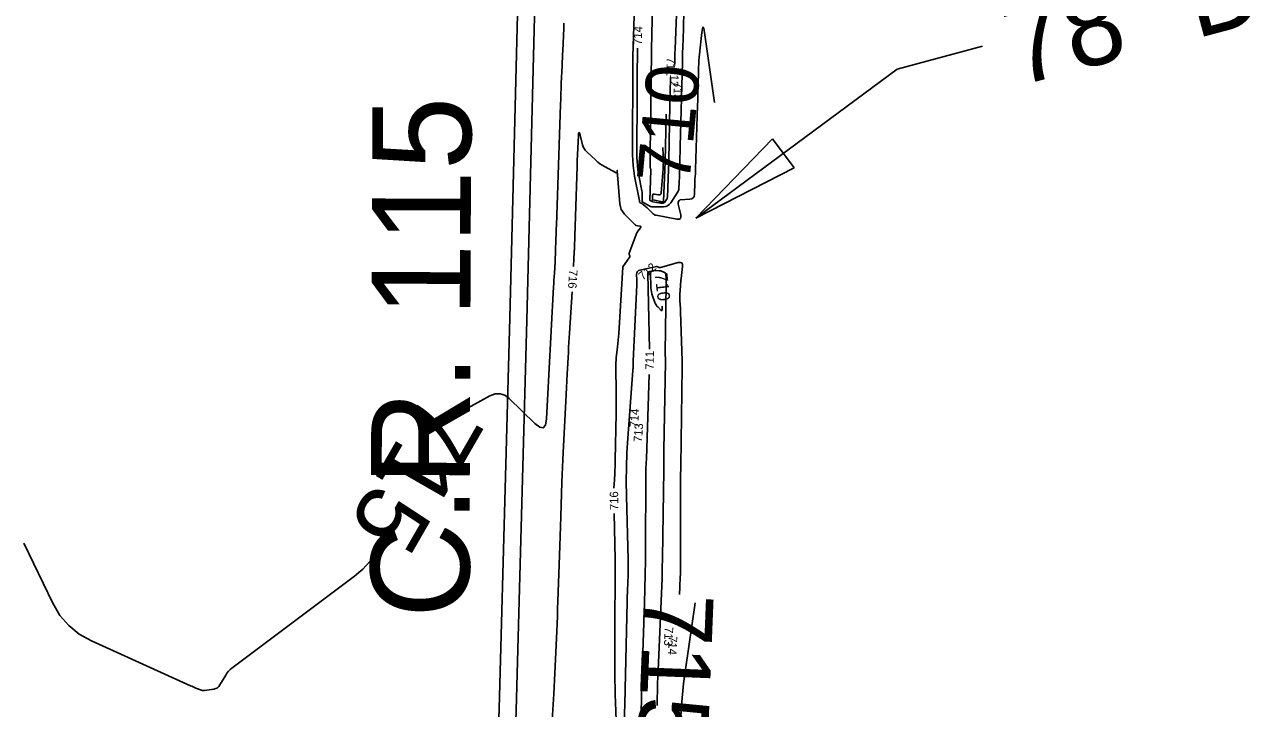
# Model space of a CAD drawing. Extents: x -361782338 to 28259792, y -263199453 to 8342113.
# Drawn here: x 1403593 to 1404176, y 577718 to 578042 of the extents above; entities that cross this region are included whole.
import ezdxf

# ---------------------------------------------------------------- set-up
doc = ezdxf.new("R2010")
doc.units = 0
for name, color, linetype in [('DT_X_Contour_Minor', 7, 'Continuous'), ('Level 19', 7, 'Continuous'), ('Level 40', 7, 'Continuous'), ('Level 56', 7, 'Continuous')]:
    doc.layers.add(name, color=color, linetype=linetype)

msp = doc.modelspace()

# ---------------------------------------------------------------- linework, layer by layer
at = {"layer": 'DT_X_Contour_Minor'}
for points in [[(1403882.24, 578075.26), (1403880.6, 578027.15), (1403880.59, 578027), (1403880.59, 578026.85), (1403880.58, 578026.7), (1403880.58, 578026.55), (1403880.57, 578026.07), (1403880.57, 578025.96), (1403880.57, 578025.86), (1403880.57, 578025.75), (1403880.57, 578025.65), (1403880.56, 578024.98), (1403880.55, 578024.84), (1403880.55, 578024.7), (1403880.55, 578024.56), (1403880.55, 578024.42), (1403880.5, 577980.69), (1403880.55, 577978.11), (1403880.74, 577975.55), (1403881.04, 577973), (1403881.47, 577970.46), (1403883.75, 577958.75), (1403883.76, 577958.69), (1403883.76, 577958.63), (1403883.77, 577958.57), (1403883.77, 577958.51), (1403883.76, 577958.31), (1403883.76, 577958.27), (1403883.77, 577958.24), (1403883.79, 577958.21), (1403883.82, 577958.18), (1403883.99, 577958.04), (1403884.03, 577958.01), (1403884.07, 577957.99), (1403884.11, 577957.96), (1403884.15, 577957.94), (1403884.93, 577957.49), (1403885.09, 577957.39), (1403885.25, 577957.29), (1403885.41, 577957.17), (1403885.56, 577957.05), (1403887.36, 577955.49), (1403887.74, 577955.15), (1403888.12, 577954.81), (1403888.49, 577954.46), (1403888.86, 577954.11), (1403890.25, 577952.74), (1403890.56, 577952.47), (1403890.9, 577952.26), (1403891.27, 577952.1), (1403891.67, 577952), (1403901.48, 577950.2), (1403902.51, 577950.15), (1403903.16, 577950.46), (1403903.43, 577951.13), (1403903.33, 577952.16)], [(1403882.87, 578031.13), (1403882.82, 578028.02), (1403882.8, 578026.91), (1403882.78, 578025.81), (1403882.77, 578024.7), (1403882.75, 578023.6), (1403882.65, 578016.61), (1403882.64, 578015.11), (1403882.62, 578013.61), (1403882.61, 578012.11), (1403882.61, 578010.61), (1403882.57, 577979.48), (1403882.61, 577977.48), (1403882.76, 577975.5), (1403882.99, 577973.52), (1403883.33, 577971.55), (1403884.88, 577963.54), (1403884.98, 577962.96), (1403885.04, 577962.38), (1403885.07, 577961.79), (1403885.07, 577961.2), (1403884.99, 577958.54), (1403884.99, 577958.5), (1403885, 577958.45), (1403885.03, 577958.42), (1403885.06, 577958.39), (1403885.18, 577958.29), (1403885.21, 577958.27), (1403885.24, 577958.25), (1403885.26, 577958.23), (1403885.29, 577958.22), (1403888.68, 577956.28), (1403888.8, 577956.22), (1403888.92, 577956.17), (1403889.05, 577956.13), (1403889.18, 577956.1), (1403889.61, 577956.02), (1403889.7, 577956.01), (1403889.8, 577956), (1403889.89, 577955.99), (1403889.99, 577955.99), (1403895.15, 577956), (1403896.2, 577956.12), (1403897.12, 577956.47), (1403897.91, 577957.05), (1403898.57, 577957.87), (1403901.99, 577963.14), (1403902.16, 577963.46), (1403902.29, 577963.79), (1403902.38, 577964.13), (1403902.42, 577964.49), (1403902.47, 577965.68), (1403902.48, 577965.94), (1403902.49, 577966.2), (1403902.5, 577966.45), (1403902.51, 577966.71), (1403902.86, 577975.56), (1403902.89, 577976.45), (1403902.92, 577977.35), (1403902.94, 577978.25), (1403902.96, 577979.14), (1403903.01, 577982.07), (1403903.03, 577982.7), (1403903.04, 577983.32), (1403903.05, 577983.95), (1403903.07, 577984.58), (1403904.09, 578024.68), (1403904.11, 578025.68), (1403904.14, 578026.68), (1403904.18, 578027.67), (1403904.21, 578028.67), (1403904.34, 578031.94), (1403904.36, 578032.63), (1403904.38, 578033.33), (1403904.4, 578034.03), (1403904.42, 578034.73), (1403905.37, 578074.7)], [(1403890.04, 578062.7), (1403889.61, 578036.78), (1403889.52, 578031.22), (1403889.43, 578025.67), (1403889.35, 578020.11), (1403889.27, 578014.56), (1403888.81, 577981.82), (1403888.8, 577981.08), (1403888.8, 577980.33), (1403888.79, 577979.58), (1403888.79, 577978.83), (1403888.79, 577975.86), (1403888.79, 577975.6), (1403888.81, 577975.34), (1403888.84, 577975.08), (1403888.89, 577974.83), (1403889.05, 577973.99), (1403889.08, 577973.81), (1403889.1, 577973.62), (1403889.11, 577973.44), (1403889.11, 577973.26), (1403888.67, 577959.12), (1403888.67, 577959.11), (1403888.68, 577959.1), (1403888.68, 577959.09), (1403888.69, 577959.08), (1403888.73, 577959.05), (1403888.73, 577959.05), (1403888.74, 577959.04), (1403888.75, 577959.04), (1403888.76, 577959.03), (1403889.44, 577958.64), (1403889.59, 577958.56), (1403889.75, 577958.5), (1403889.91, 577958.45), (1403890.07, 577958.41), (1403892.92, 577957.9), (1403893.22, 577957.85), (1403893.53, 577957.82), (1403893.84, 577957.8), (1403894.14, 577957.8), (1403895.15, 577957.8), (1403895.35, 577957.82), (1403895.53, 577957.89), (1403895.69, 577958), (1403895.82, 577958.16), (1403896.6, 577959.38), (1403896.75, 577959.65), (1403896.87, 577959.93), (1403896.94, 577960.22), (1403896.97, 577960.52), (1403897.54, 577973.69), (1403897.56, 577974.13), (1403897.58, 577974.57), (1403897.59, 577975.01), (1403897.61, 577975.44), (1403897.67, 577976.88), (1403897.68, 577977.19), (1403897.69, 577977.49), (1403897.7, 577977.8), (1403897.7, 577978.11), (1403898.36, 578012.79), (1403898.39, 578014.34), (1403898.42, 578015.89), (1403898.45, 578017.16)], [(1403900.41, 578022.93), (1403900.45, 578024.13), (1403900.51, 578026.37), (1403900.59, 578028.6), (1403900.67, 578030.84), (1403901.43, 578051.04)], [(1403797.76, 577857.75), (1403801.18, 577859.93), (1403812.96, 577866.41), (1403815.43, 577867.37), (1403817.78, 577867.48), (1403820.02, 577866.74), (1403822.14, 577865.15), (1403834.23, 577853.34), (1403836.52, 577851.57), (1403838.21, 577851.35), (1403839.3, 577852.66), (1403839.79, 577855.51), (1403843.1, 577918.08), (1403843.19, 577919.7), (1403843.28, 577921.33), (1403843.38, 577922.95), (1403843.48, 577924.57), (1403843.81, 577929.87), (1403843.87, 577931.01), (1403843.93, 577932.14), (1403843.98, 577933.28), (1403844.02, 577934.42), (1403844.24, 577941.24), (1403844.29, 577942.7), (1403844.34, 577944.16), (1403844.39, 577945.62), (1403844.44, 577947.09), (1403846.37, 578004.51), (1403846.46, 578007.03), (1403846.55, 578009.55), (1403846.65, 578012.07), (1403846.76, 578014.59), (1403847.12, 578022.82), (1403847.2, 578024.59), (1403847.28, 578026.35), (1403847.35, 578028.11), (1403847.43, 578029.88), (1403847.89, 578040.65), (1403848, 578042.96)], [(1403903.33, 577952.16), (1403902.06, 577957.31), (1403902.02, 577957.54), (1403902.03, 577957.77), (1403902.07, 577957.99), (1403902.16, 577958.21), (1403902.51, 577958.91), (1403902.59, 577959.04), (1403902.7, 577959.14), (1403902.84, 577959.2), (1403902.99, 577959.23), (1403907.69, 577959.64), (1403908.58, 577959.84), (1403909.22, 577960.27), (1403909.62, 577960.93), (1403909.77, 577961.83), (1403909.96, 577967.6), (1403909.98, 577968.21), (1403910.01, 577968.82), (1403910.05, 577969.42), (1403910.1, 577970.03), (1403910.28, 577972), (1403910.31, 577972.43), (1403910.34, 577972.85), (1403910.36, 577973.28), (1403910.37, 577973.7), (1403911.29, 578004), (1403911.36, 578006.27), (1403911.42, 578008.55), (1403911.47, 578010.83), (1403911.52, 578013.1), (1403911.68, 578020.54), (1403911.73, 578022.14), (1403911.82, 578023.73), (1403911.94, 578025.32), (1403912.09, 578026.9), (1403913.33, 578038.59), (1403913.61, 578040.47), (1403913.91, 578041.1), (1403914.24, 578040.48), (1403914.58, 578038.61), (1403919.34, 578005.4)], [(1403889.9, 577959.31), (1403889.91, 577959.31), (1403889.91, 577959.31), (1403889.91, 577959.31), (1403889.91, 577959.3), (1403889.91, 577959.3), (1403889.98, 577959.26), (1403890, 577959.25), (1403890.02, 577959.25), (1403890.03, 577959.24), (1403890.05, 577959.24), (1403894.71, 577958.41), (1403894.74, 577958.4), (1403894.77, 577958.4), (1403894.8, 577958.4), (1403894.84, 577958.4), (1403894.94, 577958.4), (1403894.96, 577958.4), (1403894.98, 577958.41), (1403895, 577958.42), (1403895.01, 577958.43), (1403895.09, 577958.56), (1403895.11, 577958.59), (1403895.12, 577958.62), (1403895.13, 577958.65), (1403895.13, 577958.68), (1403895.94, 577977.3), (1403895.94, 577977.33), (1403895.94, 577977.36), (1403895.94, 577977.38), (1403895.94, 577977.41), (1403895.95, 577977.5), (1403895.95, 577977.52), (1403895.95, 577977.54), (1403895.95, 577977.56), (1403895.95, 577977.58), (1403896.35, 577999.06), (1403896.35, 577999.86)], [(1403852.55, 577927.74), (1403852.75, 577931.49), (1403852.98, 577936.78), (1403853.17, 577942.08), (1403854.25, 577975.13), (1403854.25, 577975.39), (1403854.26, 577975.66), (1403854.27, 577975.93), (1403854.28, 577976.2), (1403854.31, 577977.07), (1403854.32, 577977.26), (1403854.32, 577977.45), (1403854.33, 577977.64), (1403854.34, 577977.83), (1403854.87, 577989.78), (1403854.96, 577990.85), (1403855.14, 577991.22), (1403855.38, 577990.89), (1403855.7, 577989.87), (1403856.86, 577985.39), (1403857.17, 577984.47), (1403857.59, 577983.61), (1403858.13, 577982.83), (1403858.79, 577982.11), (1403863.08, 577978.03), (1403864.02, 577977.19), (1403865.02, 577976.42), (1403866.06, 577975.73), (1403867.15, 577975.1), (1403872.73, 577972.13), (1403872.91, 577972.06), (1403873.03, 577972.08), (1403873.12, 577972.18), (1403873.16, 577972.36), (1403873.21, 577973.08), (1403873.22, 577973.2), (1403873.24, 577973.24), (1403873.25, 577973.2), (1403873.26, 577973.08), (1403874.49, 577957.43), (1403874.72, 577956.06), (1403875.17, 577954.79), (1403875.84, 577953.62), (1403876.74, 577952.55), (1403881.43, 577947.85), (1403881.44, 577947.84), (1403881.44, 577947.83), (1403881.45, 577947.81), (1403881.45, 577947.8), (1403881.46, 577947.75), (1403881.46, 577947.74), (1403881.47, 577947.73), (1403881.47, 577947.72), (1403881.48, 577947.71), (1403881.72, 577947.51), (1403881.75, 577947.48), (1403881.79, 577947.45), (1403881.82, 577947.42), (1403881.85, 577947.38), (1403881.96, 577947.28), (1403881.99, 577947.26), (1403882.01, 577947.24), (1403882.04, 577947.23), (1403882.07, 577947.22), (1403883.87, 577946.89), (1403884.18, 577946.79), (1403884.34, 577946.62), (1403884.34, 577946.4), (1403884.19, 577946.11), (1403883.02, 577944.45), (1403882.79, 577944.09), (1403882.57, 577943.72), (1403882.38, 577943.33), (1403882.22, 577942.93), (1403878.91, 577934.12), (1403878.86, 577933.93), (1403878.85, 577933.74), (1403878.88, 577933.55), (1403878.94, 577933.37), (1403879.23, 577932.77), (1403879.27, 577932.64), (1403879.28, 577932.52), (1403879.25, 577932.4), (1403879.18, 577932.28), (1403875.82, 577927.54), (1403875.81, 577927.52), (1403875.81, 577927.51), (1403875.82, 577927.5), (1403875.83, 577927.49), (1403875.88, 577927.46), (1403875.89, 577927.45), (1403875.89, 577927.45), (1403875.9, 577927.44), (1403875.9, 577927.42), (1403873.92, 577896.05), (1403873.81, 577894.45), (1403873.68, 577892.85), (1403873.53, 577891.26), (1403873.36, 577889.67), (1403872.77, 577884.48), (1403872.66, 577883.36)], [(1403894.87, 577984.05), (1403895.02, 577980.57), (1403895.07, 577978.94), (1403895.07, 577977.3), (1403895.02, 577975.67), (1403894.92, 577974.03), (1403894.09, 577962.65), (1403893.98, 577962.13), (1403893.72, 577961.79), (1403893.33, 577961.64), (1403892.8, 577961.66), (1403890.83, 577962.03), (1403890.46, 577962.05), (1403890.19, 577961.94), (1403890.03, 577961.7), (1403889.96, 577961.34), (1403889.9, 577959.31), (1403889.9, 577959.31), (1403889.9, 577959.31), (1403889.9, 577959.31), (1403889.9, 577959.31)], [(1403902.73, 577772.46), (1403902.78, 577773.52), (1403902.83, 577774.58), (1403902.87, 577775.64), (1403902.92, 577776.7), (1403903.07, 577780.17), (1403903.1, 577780.91), (1403903.12, 577781.65), (1403903.13, 577782.4), (1403903.14, 577783.14), (1403903.25, 577827.06), (1403903.25, 577827.67), (1403903.26, 577828.29), (1403903.26, 577828.91), (1403903.27, 577829.53), (1403903.3, 577831.55), (1403903.31, 577831.98), (1403903.32, 577832.41), (1403903.32, 577832.85), (1403903.33, 577833.28), (1403903.94, 577879.99), (1403903.94, 577880.28), (1403903.95, 577880.58), (1403903.95, 577880.88), (1403903.96, 577881.18), (1403903.97, 577882.15), (1403903.97, 577882.36), (1403903.97, 577882.57), (1403903.97, 577882.78), (1403903.96, 577882.99), (1403903.24, 577906.22), (1403903.23, 577906.38), (1403903.23, 577906.54), (1403903.23, 577906.7), (1403903.23, 577906.87), (1403903.24, 577907.4), (1403903.24, 577907.51), (1403903.24, 577907.62), (1403903.23, 577907.74), (1403903.22, 577907.85), (1403902.91, 577911.45), (1403902.86, 577912.22), (1403902.84, 577912.99), (1403902.84, 577913.76), (1403902.88, 577914.53), (1403903.17, 577918.62), (1403903.23, 577919.49), (1403903.31, 577920.36), (1403903.4, 577921.24), (1403903.5, 577922.11), (1403904.21, 577927.76), (1403904.19, 577928.79), (1403903.84, 577929.43), (1403903.16, 577929.69), (1403902.15, 577929.57), (1403893.67, 577927.33), (1403893.46, 577927.3), (1403893.26, 577927.29), (1403893.06, 577927.31), (1403892.85, 577927.36), (1403891.93, 577927.68), (1403891.92, 577927.68), (1403891.92, 577927.68), (1403891.91, 577927.68), (1403891.91, 577927.68), (1403891.88, 577927.69), (1403891.88, 577927.69), (1403891.88, 577927.69), (1403891.88, 577927.69), (1403891.88, 577927.68), (1403891.88, 577927.68), (1403891.88, 577927.68), (1403891.88, 577927.68), (1403891.88, 577927.68), (1403891.88, 577927.68), (1403884.04, 577926.03), (1403883.33, 577925.77), (1403882.82, 577925.36), (1403882.53, 577924.77), (1403882.44, 577924.02), (1403882.49, 577921.31), (1403882.5, 577920.73), (1403882.5, 577920.14), (1403882.49, 577919.56), (1403882.47, 577918.98), (1403880.84, 577882.95), (1403880.82, 577882.52), (1403880.8, 577882.08), (1403880.78, 577881.64), (1403880.77, 577881.2), (1403880.72, 577879.77), (1403880.71, 577879.47), (1403880.7, 577879.16), (1403880.68, 577878.85), (1403880.66, 577878.55), (1403878.27, 577846.35), (1403877.85, 577839.55), (1403877.6, 577832.74), (1403877.52, 577825.93), (1403877.6, 577819.11)], [(1403892.16, 577719.79), (1403892.35, 577730.26), (1403892.37, 577730.88), (1403892.38, 577731.5), (1403892.41, 577732.13), (1403892.43, 577732.75), (1403892.53, 577734.78), (1403892.55, 577735.21), (1403892.57, 577735.65), (1403892.59, 577736.08), (1403892.61, 577736.52), (1403894.5, 577780.1), (1403894.53, 577781.03), (1403894.56, 577781.97), (1403894.58, 577782.91), (1403894.58, 577783.85), (1403894.59, 577786.91), (1403894.6, 577787.57), (1403894.6, 577788.23), (1403894.61, 577788.88), (1403894.62, 577789.54), (1403895.24, 577831.44), (1403895.26, 577832.37), (1403895.27, 577833.3), (1403895.28, 577834.22), (1403895.29, 577835.15), (1403895.33, 577838.18), (1403895.34, 577838.83), (1403895.35, 577839.47), (1403895.36, 577840.12), (1403895.37, 577840.77), (1403896.06, 577882.63), (1403896.06, 577883.07), (1403896.06, 577883.5), (1403896.06, 577883.94), (1403896.04, 577884.37), (1403896, 577885.78), (1403895.99, 577886.09), (1403895.99, 577886.39), (1403895.99, 577886.69), (1403895.99, 577887), (1403896.47, 577919.31), (1403896.48, 577919.95), (1403896.46, 577920.59), (1403896.43, 577921.23), (1403896.38, 577921.87), (1403896.19, 577924.05), (1403896.12, 577924.42), (1403895.95, 577924.71), (1403895.7, 577924.94), (1403895.37, 577925.1), (1403894.14, 577925.52), (1403893.87, 577925.6), (1403893.6, 577925.67), (1403893.33, 577925.71), (1403893.05, 577925.73), (1403890.46, 577925.84), (1403890.41, 577925.84), (1403890.35, 577925.83), (1403890.3, 577925.81), (1403890.25, 577925.78), (1403890.09, 577925.67), (1403890.05, 577925.65), (1403890.01, 577925.63), (1403889.98, 577925.62), (1403889.94, 577925.6), (1403888.39, 577925.28), (1403888.11, 577925.18), (1403887.9, 577925.01), (1403887.78, 577924.77), (1403887.75, 577924.46), (1403888.46, 577888.54)], [(1403889.07, 577924.89), (1403889.21, 577917.65), (1403889.27, 577916.67), (1403889.41, 577915.7), (1403889.63, 577914.74), (1403889.93, 577913.8), (1403891.08, 577910.66), (1403891.32, 577910.07), (1403891.63, 577909.53), (1403892, 577909.02), (1403892.42, 577908.56), (1403893.91, 577907.09), (1403894.19, 577906.87), (1403894.39, 577906.84), (1403894.51, 577907), (1403894.56, 577907.35), (1403894.58, 577908.95)], [(1403842.23, 577710.14), (1403843.19, 577725.34), (1403843.39, 577728.6), (1403843.57, 577731.86), (1403843.73, 577735.12), (1403843.88, 577738.38), (1403844.6, 577754.99), (1403844.74, 577758.55), (1403844.89, 577762.11), (1403845.03, 577765.67), (1403845.16, 577769.23), (1403845.94, 577790.79), (1403846.11, 577795.41), (1403846.27, 577800.03), (1403846.42, 577804.65), (1403846.56, 577809.27), (1403847.06, 577825.66), (1403847.18, 577829.18), (1403847.32, 577832.69), (1403847.47, 577836.2), (1403847.64, 577839.71), (1403848.89, 577863.95), (1403849.06, 577867.16), (1403849.22, 577870.36), (1403849.39, 577873.56), (1403849.56, 577876.77), (1403850.11, 577887.23), (1403850.23, 577889.48), (1403850.36, 577891.72), (1403850.49, 577893.96), (1403850.63, 577896.2), (1403851.85, 577915.76)], [(1403872.66, 577883.36), (1403872.59, 577882.25), (1403872.55, 577881.13), (1403872.55, 577880.01), (1403872.73, 577868.19), (1403872.76, 577865.65), (1403872.77, 577863.12), (1403872.75, 577860.58), (1403872.72, 577858.05), (1403872.3, 577836.07), (1403872.26, 577834.45), (1403872.21, 577832.83), (1403872.14, 577831.21), (1403872.05, 577829.59), (1403871.75, 577824.3), (1403871.7, 577823.17), (1403871.69, 577822.81)], [(1403888.35, 577876.54), (1403887.05, 577836.61), (1403887.02, 577836.01), (1403887, 577835.4), (1403886.96, 577834.79), (1403886.92, 577834.18), (1403886.77, 577832.2), (1403886.75, 577831.78), (1403886.73, 577831.35), (1403886.72, 577830.93), (1403886.73, 577830.5), (1403886.78, 577828.33), (1403886.79, 577827.86), (1403886.8, 577827.39), (1403886.8, 577826.93), (1403886.8, 577826.46), (1403886.64, 577795.21), (1403886.58, 577788.51), (1403886.47, 577781.82), (1403886.32, 577775.12), (1403886.12, 577768.43), (1403885.03, 577735.48), (1403885.02, 577735.1), (1403885.01, 577734.72), (1403885, 577734.35), (1403884.99, 577733.97), (1403884.96, 577732.74), (1403884.95, 577732.47), (1403884.95, 577732.21), (1403884.94, 577731.95), (1403884.93, 577731.68), (1403884.14, 577692.52)], [(1403877.6, 577819.11), (1403878.37, 577788.79), (1403878.38, 577788.04), (1403878.39, 577787.29), (1403878.4, 577786.54), (1403878.4, 577785.79), (1403878.38, 577783.33), (1403878.38, 577782.81), (1403878.37, 577782.28), (1403878.36, 577781.75), (1403878.34, 577781.23), (1403878.25, 577778.34), (1403878.23, 577777.72), (1403878.21, 577777.11), (1403878.19, 577776.49), (1403878.18, 577775.87), (1403877.15, 577734.55), (1403877.11, 577733.16), (1403877.08, 577731.78), (1403877.05, 577730.39), (1403877.02, 577729), (1403876.93, 577724.48), (1403876.91, 577723.5), (1403876.88, 577722.53), (1403876.86, 577721.56), (1403876.83, 577720.59), (1403875.28, 577673.26)], [(1403871.83, 577810.81), (1403872.21, 577789.18), (1403872.26, 577785.72), (1403872.29, 577782.26), (1403872.29, 577778.8), (1403872.26, 577775.34), (1403872.14, 577764.04), (1403872.12, 577761.61), (1403872.11, 577759.19), (1403872.1, 577756.77), (1403872.09, 577754.35), (1403872.09, 577738.55), (1403872.1, 577735.17), (1403872.15, 577731.78), (1403872.22, 577728.4), (1403872.33, 577725.02), (1403873.33, 577697.02)], [(1403592.31, 577796.77), (1403606.02, 577768.21), (1403609.37, 577762.5), (1403613.52, 577757.63), (1403618.49, 577753.58), (1403624.27, 577750.37), (1403671.13, 577729.2), (1403671.78, 577728.9), (1403672.43, 577728.62), (1403673.08, 577728.34), (1403673.74, 577728.06), (1403675.89, 577727.16), (1403676.35, 577727.01), (1403676.83, 577726.91), (1403677.31, 577726.89), (1403677.8, 577726.93), (1403682.26, 577727.61), (1403683.15, 577727.84), (1403683.93, 577728.25), (1403684.6, 577728.83), (1403685.14, 577729.58), (1403687.83, 577734.2), (1403688.45, 577735.16), (1403689.16, 577736.04), (1403689.95, 577736.84), (1403690.82, 577737.56), (1403748.88, 577781.09), (1403752.75, 577784.36), (1403756.15, 577788.02)], [(1403902.84, 577708.51), (1403903.98, 577723.47), (1403904.27, 577726.82), (1403904.62, 577730.16), (1403905.02, 577733.5), (1403905.49, 577736.82), (1403910.2, 577768.45)]]:
    msp.add_lwpolyline(points, dxfattribs=at)
at = {"layer": 'Level 40'}
for p, q in [((1403910.46, 577950.59), (1403946.79, 577988.19)), ((1403946.79, 577988.19), (1403957.02, 577974.39)), ((1403957.02, 577974.39), (1403910.46, 577950.59))]:
    msp.add_line(p, q, dxfattribs=at)
msp.add_lwpolyline([(1403910.46, 577950.59), (1404005.8, 578021.25), (1404046.12, 578032.06)], dxfattribs=at)
at = {"layer": 'Level 56'}
for points in [[(1403799.72, 576951.13), (1403799.37, 577003.24), (1403799.52, 577053.24), (1403800.45, 577093.03), (1403801.13, 577118.22), (1403803.77, 577203.2), (1403806.32, 577303.59), (1403809.79, 577453.55), (1403811.89, 577528.32), (1403813.35, 577578.3), (1403815.32, 577653.47), (1403817.33, 577718.44), (1403820.35, 577828.2), (1403822.42, 577903.37), (1403824.98, 578003.34), (1403826.21, 578053.33), (1403828.88, 578143.09), (1403833.01, 578278.03), (1403835.33, 578353.19), (1403836.58, 578403.18), (1403837.59, 578489.24)], [(1403807.71, 576950.11), (1403807.36, 577002.22), (1403807.51, 577052.22), (1403808.43, 577092.01), (1403809.12, 577117.2), (1403811.75, 577202.18), (1403814.31, 577302.57), (1403817.77, 577452.53), (1403819.88, 577527.3), (1403821.33, 577577.28), (1403823.31, 577652.45), (1403825.32, 577717.42), (1403828.34, 577827.18), (1403830.4, 577902.36), (1403832.96, 578002.32), (1403834.2, 578052.31), (1403836.87, 578142.07), (1403841, 578277.01), (1403843.32, 578352.18), (1403844.57, 578402.16), (1403845.58, 578488.22)]]:
    msp.add_lwpolyline(points, dxfattribs=at)

# ---------------------------------------------------------------- texts
at = {"layer": 'Level 19'}
for s, height, rotation, p in [('714', 4, 88.47463, (1403884.87, 578032.61)), ('710', 25, 84.63308, (1403907.33, 577966.44)), ('711', 4, 268.38406, (1403896.71, 578026.87)), ('712', 4, 268.54033, (1403898.38, 578021.62)), ('713', 4, 268.54595, (1403900.04, 578015.39)), ('712', 4, 40.73796, (1403885.36, 577920.97)), ('716', 4, 266.61449, (1403850.48, 577926.33)), ('710', 6, 276.47644, (1403890.97, 577924.37)), ('711', 4, 89.46093, (1403890.51, 577878.87)), ('715', 33, 240.05986, (1403782.38, 577869.14)), ('714', 4, 85.75882, (1403883.03, 577851.34)), ('713', 4, 85.91877, (1403884.92, 577844.42)), ('716', 4, 90.647, (1403873.77, 577812.36)), ('715', 33, 267.72238, (1403885.96, 577773.55)), ('713', 4, 267.33873, (1403895.78, 577757.07)), ('714', 4, 267.26691, (1403897.69, 577752.77))]:
    msp.add_text(s, height=height, rotation=rotation, dxfattribs=at).set_placement(p)
at = {"layer": 'Level 40'}
for s, height, rotation, p in [('78" D', 37.5, 15, (1404062.6, 578012.9)), ('C.R. 115', 46.8, 89.77825, (1403803.18, 577761.15))]:
    msp.add_text(s, height=height, rotation=rotation, dxfattribs=at).set_placement(p)

doc.saveas('drawing.dxf')
